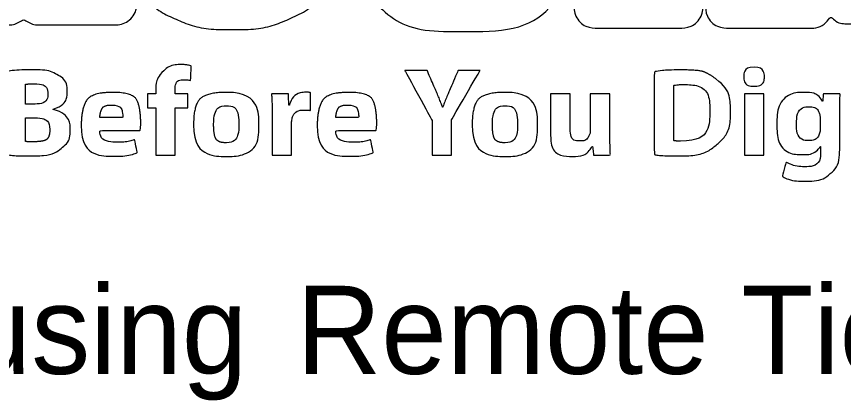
# Model space of a CAD drawing. Extents: x 0 to 34, y 0 to 22.
# Drawn here: x 3.42 to 4.735, y 1.535 to 2.145 of the extents above; entities that cross this region are included whole.
import ezdxf

# ---------------------------------------------------------------- set-up
doc = ezdxf.new("R2010")
doc.units = 0
doc.layers.add('Default', color=7, linetype='Continuous')
doc.layers.add('SH_Data', color=7, linetype='Continuous')

msp = doc.modelspace()

# ---------------------------------------------------------------- linework, layer by layer
at = {"layer": 'Default'}
for p, q in [((4.5771, 2.0226), (4.5771, 1.9252)), ((4.6081, 2.0226), (4.5771, 2.0226)), ((4.6081, 1.9252), (4.6081, 2.0226)), ((4.5771, 1.9252), (4.6081, 1.9252))]:
    msp.add_line(p, q, dxfattribs=at)
for points, degree in [([(4.2638, 2.6669), (4.2321, 2.6974), (4.1879, 2.7122), (4.1288, 2.7122), (4.0179, 2.7122), (3.9544, 2.6564), (3.9483, 2.5549), (3.942, 2.5861), (3.9326, 2.6121), (3.9196, 2.6338), (3.9033, 2.6613), (3.8811, 2.6817), (3.8538, 2.6946), (3.8285, 2.7066), (3.7981, 2.7127), (3.7633, 2.7127), (3.7285, 2.7127), (3.6981, 2.7066), (3.6729, 2.6946), (3.6481, 2.6829), (3.6279, 2.6647), (3.6121, 2.6409), (3.6121, 2.6409), (3.6121, 2.6611), (3.6121, 2.6611), (3.6121, 2.6842), (3.5932, 2.7031), (3.57, 2.7031), (3.57, 2.7031), (3.4577, 2.7031), (3.4577, 2.7031), (3.4478, 2.7031), (3.439, 2.6991), (3.4317, 2.6933), (3.4245, 2.6991), (3.4157, 2.7031), (3.4058, 2.7031), (3.4058, 2.7031), (3.2935, 2.7031), (3.2935, 2.7031), (3.2792, 2.7031), (3.2667, 2.6961), (3.2591, 2.6852), (3.2514, 2.6961), (3.2389, 2.7031), (3.2247, 2.7031), (3.2247, 2.7031), (3.1124, 2.7031), (3.1124, 2.7031), (3.0892, 2.7031), (3.0704, 2.6843), (3.0704, 2.6611), (3.0704, 2.6611), (3.0704, 2.6349), (3.0704, 2.6349), (3.054, 2.6618), (3.0323, 2.6819), (3.0053, 2.6946), (2.9801, 2.7066), (2.9496, 2.7127), (2.9148, 2.7127), (2.88, 2.7127), (2.8496, 2.7066), (2.8244, 2.6946), (2.797, 2.6817), (2.7749, 2.6613), (2.7585, 2.6338), (2.7438, 2.6091), (2.7332, 2.5777), (2.7272, 2.5406), (2.7216, 2.5064), (2.7188, 2.4649), (2.7188, 2.4175), (2.7188, 2.3702), (2.7216, 2.3287), (2.7272, 2.2945), (2.7332, 2.2574), (2.7438, 2.226), (2.7585, 2.2013), (2.7751, 2.1734), (2.7977, 2.1531), (2.8254, 2.141), (2.8503, 2.13), (2.8804, 2.1245), (2.9147, 2.1245), (2.949, 2.1245), (2.9791, 2.13), (3.004, 2.141), (3.0315, 2.153), (3.0537, 2.1729), (3.0703, 2.2002), (3.0703, 2.2002), (3.0703, 2.174), (3.0703, 2.174), (3.0703, 2.1509), (3.0891, 2.132), (3.1123, 2.132), (3.1123, 2.132), (3.2246, 2.132), (3.2246, 2.132), (3.2388, 2.132), (3.2514, 2.139), (3.259, 2.1499), (3.2666, 2.139), (3.2791, 2.132), (3.2934, 2.132), (3.2934, 2.132), (3.4057, 2.132), (3.4057, 2.132), (3.4156, 2.132), (3.4244, 2.136), (3.4317, 2.1418), (3.4389, 2.136), (3.4477, 2.132), (3.4576, 2.132), (3.4576, 2.132), (3.5699, 2.132), (3.5699, 2.132), (3.5931, 2.132), (3.612, 2.1508), (3.612, 2.174), (3.612, 2.174), (3.612, 2.1942), (3.612, 2.1942), (3.628, 2.1701), (3.6487, 2.152), (3.6739, 2.141), (3.6988, 2.13), (3.7289, 2.1245), (3.7632, 2.1245), (3.7975, 2.1245), (3.8276, 2.13), (3.8526, 2.141), (3.8803, 2.1531), (3.9029, 2.1734), (3.9194, 2.2012), (3.9301, 2.2192), (3.9384, 2.2401), (3.9446, 2.2644), (3.9498, 2.2242), (3.9648, 2.1916), (3.9899, 2.1676), (4.0221, 2.1365), (4.0674, 2.1214), (4.1286, 2.1214), (4.2145, 2.1214), (4.2721, 2.1544), (4.2979, 2.2149), (4.2979, 2.2149), (4.3064, 2.2149), (4.3064, 2.2149), (4.3064, 2.2149), (4.3064, 2.1675), (4.3064, 2.1675), (4.3064, 2.1451), (4.3246, 2.1269), (4.3469, 2.1269), (4.3469, 2.1269), (4.4708, 2.1269), (4.4708, 2.1269), (4.4931, 2.1269), (4.5113, 2.1451), (4.5113, 2.1675), (4.5113, 2.1675), (4.5113, 2.4395), (4.5113, 2.4395), (4.5127, 2.4395), (4.5139, 2.4393), (4.5153, 2.4393), (4.5153, 2.4393), (4.5153, 2.1675), (4.5153, 2.1675), (4.5153, 2.1451), (4.5335, 2.1269), (4.5559, 2.1269), (4.5559, 2.1269), (4.6797, 2.1269), (4.6797, 2.1269), (4.6945, 2.1269), (4.7074, 2.135), (4.7145, 2.1469), (4.7202, 2.139), (4.7295, 2.1339), (4.7401, 2.1339), (4.7401, 2.1339), (4.8104, 2.1339), (4.8104, 2.1339), (4.828, 2.1339), (4.8423, 2.1481), (4.8423, 2.1657), (4.8423, 2.1657), (4.8423, 2.1942), (4.8423, 2.1942), (4.8437, 2.1908), (4.8446, 2.1873), (4.8463, 2.1842), (4.8558, 2.1663), (4.87, 2.1523), (4.8885, 2.1425), (4.9062, 2.1332), (4.9282, 2.1286), (4.9558, 2.1286), (4.9833, 2.1286), (5.0051, 2.1338), (5.0227, 2.144), (5.04, 2.1541), (5.0534, 2.168), (5.0629, 2.1851), (5.0629, 2.1851), (5.0629, 2.1657), (5.0629, 2.1657), (5.0629, 2.1481), (5.0771, 2.1339), (5.0947, 2.1339), (5.0947, 2.1339), (5.1702, 2.1339), (5.1702, 2.1339), (5.1878, 2.1339), (5.202, 2.1481), (5.202, 2.1657), (5.202, 2.1657), (5.202, 2.3054), (5.202, 2.3054), (5.202, 2.3134), (5.2031, 2.317), (5.2029, 2.3174), (5.2045, 2.3183), (5.211, 2.3193), (5.2183, 2.3187), (5.2206, 2.3185), (5.2228, 2.3181), (5.2253, 2.3177), (5.2268, 2.3174), (5.2283, 2.3179), (5.2299, 2.3178), (5.2297, 2.3116), (5.2292, 2.306), (5.2292, 2.2993), (5.2292, 2.2699), (5.2315, 2.2462), (5.2362, 2.2271), (5.2409, 2.2078), (5.2471, 2.1926), (5.255, 2.1805), (5.252, 2.1789), (5.2492, 2.1769), (5.2468, 2.1744), (5.2408, 2.1684), (5.2375, 2.16), (5.2377, 2.1515), (5.238, 2.1324), (5.2416, 2.1158), (5.2483, 2.1023), (5.2554, 2.088), (5.2654, 2.0765), (5.278, 2.0679), (5.2895, 2.0602), (5.3028, 2.0548), (5.3175, 2.052), (5.33, 2.0495), (5.3435, 2.0482), (5.3576, 2.0482), (5.3736, 2.0482), (5.3889, 2.0501), (5.403, 2.0538), (5.419, 2.058), (5.433, 2.0651), (5.445, 2.0748), (5.4576, 2.085), (5.4674, 2.0986), (5.4744, 2.1151), (5.4809, 2.1306), (5.4843, 2.1491), (5.4843, 2.17), (5.4843, 2.17), (5.4843, 2.4219), (5.4843, 2.4219), (5.4843, 2.4395), (5.47, 2.4538), (5.4524, 2.4538), (5.4524, 2.4538), (5.4524, 2.4537), (5.4524, 2.4537)], 3), ([(3.6542, 2.0591), (3.6542, 2.0591), (3.6542, 2.0591), (3.6542, 2.0591), (3.6619, 2.0662), (3.6726, 2.0689), (3.6816, 2.0689), (3.6886, 2.0689), (3.6938, 2.0681), (3.6981, 2.0669), (3.6981, 2.0669), (3.6969, 2.0436), (3.6969, 2.0436), (3.6942, 2.0443), (3.691, 2.0449), (3.6869, 2.0449), (3.6767, 2.0449), (3.6724, 2.0372), (3.6724, 2.0276), (3.6724, 2.0276), (3.6724, 2.0226), (3.6724, 2.0226), (3.6724, 2.0226), (3.6924, 2.0226), (3.6924, 2.0226), (3.6924, 2.0226), (3.6924, 2.0004), (3.6924, 2.0004), (3.6924, 2.0004), (3.6726, 2.0004), (3.6726, 2.0004), (3.6726, 2.0004), (3.6726, 1.9252), (3.6726, 1.9252), (3.6726, 1.9252), (3.6416, 1.9252), (3.6416, 1.9252), (3.6416, 1.9252), (3.6416, 2.0004), (3.6416, 2.0004), (3.6416, 2.0004), (3.6286, 2.0004), (3.6286, 2.0004), (3.6286, 2.0004), (3.6286, 2.0226), (3.6286, 2.0226), (3.6286, 2.0226), (3.6416, 2.0226), (3.6416, 2.0226), (3.6416, 2.0226), (3.6416, 2.0265), (3.6416, 2.0265), (3.6416, 2.0382), (3.6452, 2.0511), (3.6542, 2.0591)], 3), ([(4.5925, 2.0651), (4.6025, 2.0651), (4.6088, 2.0585), (4.609, 2.0497), (4.609, 2.0413), (4.6021, 2.0346), (4.5923, 2.0346), (4.5826, 2.0346), (4.5761, 2.0413), (4.5763, 2.0497), (4.5761, 2.0585), (4.5826, 2.0651), (4.5925, 2.0651)], 3), ([(3.4785, 1.9979), (3.4939, 2.0035), (3.501, 2.0146), (3.501, 2.0267), (3.501, 2.0387), (3.4941, 2.048), (3.4846, 2.0529), (3.4746, 2.0587), (3.463, 2.0606), (3.4442, 2.0606), (3.4287, 2.0606), (3.4122, 2.0594), (3.4041, 2.0577), (3.4041, 2.0577), (3.4041, 1.9258), (3.4041, 1.9258), (3.411, 1.9248), (3.4224, 1.9238), (3.4376, 1.9238), (3.4649, 1.9238), (3.4816, 1.9282), (3.4916, 1.936), (3.5001, 1.9427), (3.5057, 1.9523), (3.5057, 1.9645), (3.5057, 1.9819), (3.4941, 1.9934), (3.4785, 1.9976)], 3), ([(4.1221, 2.0595), (4.1221, 2.0595), (4.1222, 2.0595), (4.1222, 2.0595), (4.1222, 2.0595), (4.157, 2.0595), (4.157, 2.0595), (4.157, 2.0595), (4.1118, 1.9811), (4.1118, 1.9811), (4.1118, 1.9811), (4.1118, 1.9251), (4.1118, 1.9251), (4.1118, 1.9251), (4.0809, 1.9251), (4.0809, 1.9251), (4.0809, 1.9251), (4.0809, 1.9801), (4.0809, 1.9801), (4.0809, 1.9801), (4.0376, 2.0595), (4.0376, 2.0595), (4.0376, 2.0595), (4.073, 2.0595), (4.073, 2.0595), (4.073, 2.0595), (4.087, 2.0272), (4.087, 2.0272), (4.0913, 2.0175), (4.094, 2.0103), (4.0975, 2.0015), (4.0975, 2.0015), (4.0979, 2.0015), (4.0979, 2.0015), (4.101, 2.0099), (4.1042, 2.0177), (4.1083, 2.0272), (4.1083, 2.0272), (4.1221, 2.0595), (4.1221, 2.0595)], 3), ([(4.4757, 2.0605), (4.4601, 2.0605), (4.4452, 2.0595), (4.4339, 2.0576), (4.4339, 2.0576), (4.4339, 1.9257), (4.4339, 1.9257), (4.4416, 1.9247), (4.453, 1.9237), (4.4691, 1.9237), (4.496, 1.9237), (4.5179, 1.9293), (4.5323, 1.941), (4.5455, 1.952), (4.5551, 1.9698), (4.5551, 1.9955), (4.5551, 2.0192), (4.5461, 2.0357), (4.5319, 2.0461)], 3), ([(4.5319, 2.0461), (4.5187, 2.0559), (4.5018, 2.0605), (4.4757, 2.0605)], 2), ([(3.448, 2.0384), (3.4619, 2.0384), (3.47, 2.033), (3.47, 2.0228), (3.47, 2.0127), (3.4612, 2.0063), (3.4449, 2.0063), (3.4449, 2.0063), (3.4348, 2.0063), (3.4348, 2.0063), (3.4348, 2.0063), (3.4348, 2.0376), (3.4348, 2.0376), (3.4348, 2.0376), (3.4348, 2.0376), (3.4348, 2.0376)], 3), ([(3.4348, 2.0376), (3.4374, 2.038), (3.4412, 2.0384), (3.448, 2.0384)], 2), ([(3.5734, 2.0248), (3.5388, 2.0248), (3.5232, 1.9975), (3.5232, 1.9728)], 2), ([(3.5734, 2.0248), (3.5734, 2.0248), (3.5734, 2.0248), (3.5734, 2.0248)], 2), ([(3.5734, 2.0248), (3.5734, 2.0248), (3.5734, 2.0248), (3.5734, 2.0248)], 2), ([(3.5734, 2.0248), (3.5734, 2.0248), (3.5734, 2.0248), (3.5734, 2.0248)], 2), ([(3.6177, 1.9761), (3.6177, 2.0003), (3.6055, 2.0248), (3.5734, 2.0248)], 2), ([(3.7017, 1.9732), (3.7017, 1.9417), (3.724, 1.923), (3.7531, 1.923), (3.7797, 1.923), (3.8055, 1.9393), (3.8055, 1.975), (3.8055, 2.0043), (3.7852, 2.0248), (3.7547, 2.0248)], 3), ([(3.7547, 2.0248), (3.7228, 2.0248), (3.7017, 2.0047), (3.7017, 1.9732)], 2), ([(3.8541, 2.0047), (3.8541, 2.0047), (3.8541, 2.0048), (3.8541, 2.0048), (3.8592, 2.0189), (3.8714, 2.0249), (3.881, 2.0249), (3.8838, 2.0249), (3.8853, 2.0249), (3.8875, 2.0245), (3.8875, 2.0245), (3.8875, 1.996), (3.8875, 1.996), (3.8853, 1.9964), (3.8827, 1.9967), (3.8792, 1.9967), (3.8678, 1.9967), (3.8601, 1.9908), (3.858, 1.9814), (3.8576, 1.9794), (3.8574, 1.977), (3.8574, 1.9747), (3.8574, 1.9747), (3.8574, 1.9252), (3.8574, 1.9252), (3.8574, 1.9252), (3.8265, 1.9252), (3.8265, 1.9252), (3.8265, 1.9252), (3.8265, 1.9906), (3.8265, 1.9906), (3.8265, 2.0049), (3.8261, 2.0142), (3.8257, 2.0226), (3.8257, 2.0226), (3.8524, 2.0226), (3.8524, 2.0226), (3.8524, 2.0226), (3.8533, 2.0047), (3.8533, 2.0047), (3.8533, 2.0047), (3.8541, 2.0047), (3.8541, 2.0047)], 3), ([(3.9485, 2.0248), (3.9139, 2.0248), (3.8983, 1.9975), (3.8983, 1.9728)], 2), ([(3.9485, 2.0248), (3.9485, 2.0248), (3.9484, 2.0248), (3.9484, 2.0248)], 2), ([(3.9484, 2.0248), (3.9484, 2.0248), (3.9484, 2.0248), (3.9485, 2.0248)], 2), ([(3.9485, 2.0248), (3.9485, 2.0248), (3.9485, 2.0248), (3.9485, 2.0248)], 2), ([(3.9928, 1.9761), (3.9928, 2.0003), (3.9806, 2.0248), (3.9485, 2.0248)], 2), ([(4.1446, 1.9732), (4.1446, 1.9417), (4.167, 1.923), (4.1961, 1.923), (4.2227, 1.923), (4.2485, 1.9393), (4.2485, 1.975), (4.2485, 2.0043), (4.2282, 2.0248), (4.1977, 2.0248)], 3), ([(4.1977, 2.0248), (4.1658, 2.0248), (4.1446, 2.0047), (4.1446, 1.9732)], 2), ([(4.465, 1.9481), (4.465, 1.9481), (4.465, 2.0359), (4.465, 2.0359), (4.4676, 2.0365), (4.4721, 2.0371), (4.479, 2.0371), (4.5056, 2.0371), (4.5223, 2.0224), (4.5221, 1.9945), (4.5221, 1.9624), (4.5038, 1.9473), (4.4756, 1.9475)], 3), ([(4.7013, 2.011), (4.6962, 2.019), (4.6877, 2.0248), (4.674, 2.0248), (4.6496, 2.0248), (4.6289, 2.0049), (4.6289, 1.9736), (4.6289, 1.9455), (4.6464, 1.926), (4.671, 1.926), (4.6824, 1.926), (4.6919, 1.9306), (4.6979, 1.9388), (4.6979, 1.9388), (4.6983, 1.9388), (4.6983, 1.9388), (4.6983, 1.9388), (4.6983, 1.9324), (4.6983, 1.9324), (4.6983, 1.9146), (4.6871, 1.9067), (4.6725, 1.9067), (4.6608, 1.9067), (4.6499, 1.9106), (4.6435, 1.9141), (4.6435, 1.9141), (4.6375, 1.8912), (4.6375, 1.8912), (4.6465, 1.8862), (4.6602, 1.8836), (4.6732, 1.8836), (4.6879, 1.8836), (4.7028, 1.8864), (4.7137, 1.8955), (4.7248, 1.9053), (4.7287, 1.9206), (4.7287, 1.9394), (4.7287, 1.9394), (4.7287, 1.9938), (4.7287, 1.9938), (4.7287, 2.0084), (4.7291, 2.0165), (4.7295, 2.0227), (4.7295, 2.0227), (4.7027, 2.0227), (4.7027, 2.0227), (4.7027, 2.0227), (4.7017, 2.0112), (4.7017, 2.0112), (4.7017, 2.0112), (4.7017, 2.011), (4.7017, 2.011)], 3), ([(4.3633, 2.0226), (4.3633, 2.0226), (4.3635, 2.0226), (4.3635, 2.0226), (4.3635, 2.0226), (4.3635, 1.9565), (4.3635, 1.9565), (4.3635, 1.9438), (4.3638, 1.9334), (4.3642, 1.9252), (4.3642, 1.9252), (4.3374, 1.9252), (4.3374, 1.9252), (4.3374, 1.9252), (4.3359, 1.939), (4.3359, 1.939), (4.3359, 1.939), (4.3353, 1.939), (4.3353, 1.939), (4.3315, 1.933), (4.3221, 1.9231), (4.3042, 1.9231), (4.2841, 1.9231), (4.2692, 1.9354), (4.2692, 1.9655), (4.2692, 1.9655), (4.2692, 2.0226), (4.2692, 2.0226), (4.2692, 2.0226), (4.3003, 2.0226), (4.3003, 2.0226), (4.3003, 2.0226), (4.3003, 1.9703), (4.3003, 1.9703), (4.3003, 1.9562), (4.305, 1.9476), (4.3158, 1.9476), (4.3243, 1.9476), (4.3292, 1.9534), (4.3312, 1.9581), (4.332, 1.9599), (4.3322, 1.9623), (4.3322, 1.9647), (4.3322, 1.9647), (4.3322, 2.0226), (4.3322, 2.0226), (4.3322, 2.0226), (4.3633, 2.0226), (4.3633, 2.0226)], 3), ([(4.7017, 2.011), (4.7017, 2.011), (4.7013, 2.011), (4.7013, 2.011)], 2), ([(3.4785, 1.9976), (3.4785, 1.9977), (3.4785, 1.9979), (3.4785, 1.9979)], 2), ([(3.5717, 2.0047), (3.586, 2.0047), (3.5892, 1.9923), (3.5892, 1.9849), (3.5892, 1.9849), (3.5525, 1.9849), (3.5525, 1.9849)], 3), ([(3.5525, 1.9849), (3.5533, 1.9931), (3.5586, 2.0047), (3.5717, 2.0047)], 2), ([(3.7336, 1.974), (3.7336, 1.9883), (3.7391, 2.0033), (3.7539, 2.0033), (3.7679, 2.0033), (3.7737, 1.9885), (3.7737, 1.974), (3.7737, 1.9564), (3.766, 1.9447), (3.7539, 1.9447)], 3), ([(3.9468, 2.0047), (3.961, 2.0047), (3.9642, 1.9923), (3.9642, 1.9849), (3.9642, 1.9849), (3.9276, 1.9849), (3.9276, 1.9849)], 3), ([(3.9276, 1.9849), (3.9284, 1.9931), (3.9337, 2.0047), (3.9468, 2.0047)], 2), ([(4.1766, 1.974), (4.1766, 1.9883), (4.1821, 2.0033), (4.1969, 2.0033), (4.2109, 2.0033), (4.2167, 1.9885), (4.2167, 1.974), (4.2167, 1.9564), (4.209, 1.9447), (4.1969, 1.9447)], 3), ([(4.6978, 1.9686), (4.6978, 1.9661), (4.6976, 1.9628), (4.6967, 1.9606), (4.6946, 1.9535), (4.6884, 1.9483), (4.6805, 1.9483), (4.6675, 1.9483), (4.6601, 1.9596), (4.6601, 1.9742), (4.6601, 1.992), (4.6693, 2.0018), (4.6805, 2.0018), (4.689, 2.0018), (4.6949, 1.9965), (4.6972, 1.9884), (4.6976, 1.9869), (4.6978, 1.9848), (4.6978, 1.9829)], 3), ([(3.4348, 1.9467), (3.4348, 1.9467), (3.4348, 1.9846), (3.4348, 1.9846), (3.4348, 1.9846), (3.4453, 1.9846), (3.4453, 1.9846), (3.4608, 1.9846), (3.4732, 1.9793), (3.4732, 1.9657)], 3), ([(3.5232, 1.9728), (3.5232, 1.9423), (3.5426, 1.9232), (3.5763, 1.9232), (3.5897, 1.9232), (3.6021, 1.9251), (3.6122, 1.9291), (3.6122, 1.9291), (3.6081, 1.9496), (3.6081, 1.9496), (3.5998, 1.947), (3.5912, 1.9456), (3.5807, 1.9456), (3.5662, 1.9456), (3.5536, 1.9516), (3.5526, 1.9642), (3.5526, 1.9642), (3.6167, 1.9642), (3.6167, 1.9642), (3.6171, 1.9664), (3.6177, 1.9709), (3.6177, 1.9761)], 3), ([(3.7539, 1.9447), (3.7408, 1.9447), (3.7336, 1.9572), (3.7336, 1.974)], 2), ([(3.8983, 1.9728), (3.8983, 1.9423), (3.9176, 1.9232), (3.9513, 1.9232), (3.9647, 1.9232), (3.9771, 1.9251), (3.9873, 1.9291), (3.9873, 1.9291), (3.9832, 1.9496), (3.9832, 1.9496), (3.9749, 1.947), (3.9663, 1.9456), (3.9557, 1.9456), (3.9413, 1.9456), (3.9287, 1.9516), (3.9277, 1.9642), (3.9277, 1.9642), (3.9918, 1.9642), (3.9918, 1.9642), (3.9922, 1.9664), (3.9928, 1.9709), (3.9928, 1.9761)], 3), ([(4.1969, 1.9447), (4.1837, 1.9447), (4.1766, 1.9572), (4.1766, 1.974)], 2), ([(4.6978, 1.9829), (4.6978, 1.9829), (4.6978, 1.9699), (4.6978, 1.9686)], 2), ([(3.4732, 1.9657), (3.4732, 1.9521), (3.4608, 1.9463), (3.4468, 1.9463)], 2), ([(3.4468, 1.9463), (3.4415, 1.9463), (3.4379, 1.9463), (3.4348, 1.9467)], 2), ([(4.4756, 1.9475), (4.4718, 1.9475), (4.4676, 1.9475), (4.465, 1.9481)], 2)]:
    msp.add_open_spline(points, degree=degree, dxfattribs=at)

# ---------------------------------------------------------------- texts
at = {"layer": 'SH_Data'}
for s, p in [('Notify online using ', (2.2574, 1.5774)), ('Remote Ticket Entry', (3.8649, 1.5774))]:
    msp.add_text(s, height=0.14, dxfattribs=at).set_placement(p)

doc.saveas('drawing.dxf')
